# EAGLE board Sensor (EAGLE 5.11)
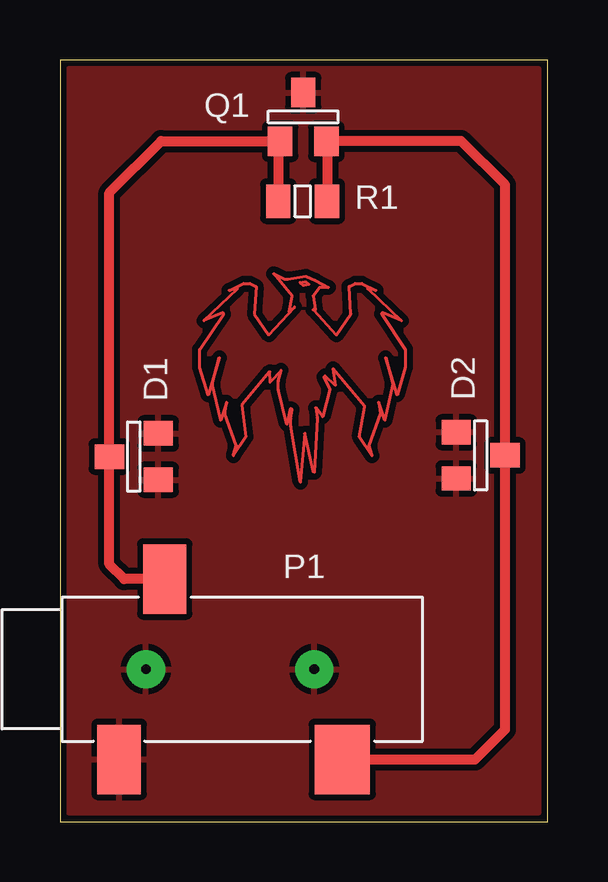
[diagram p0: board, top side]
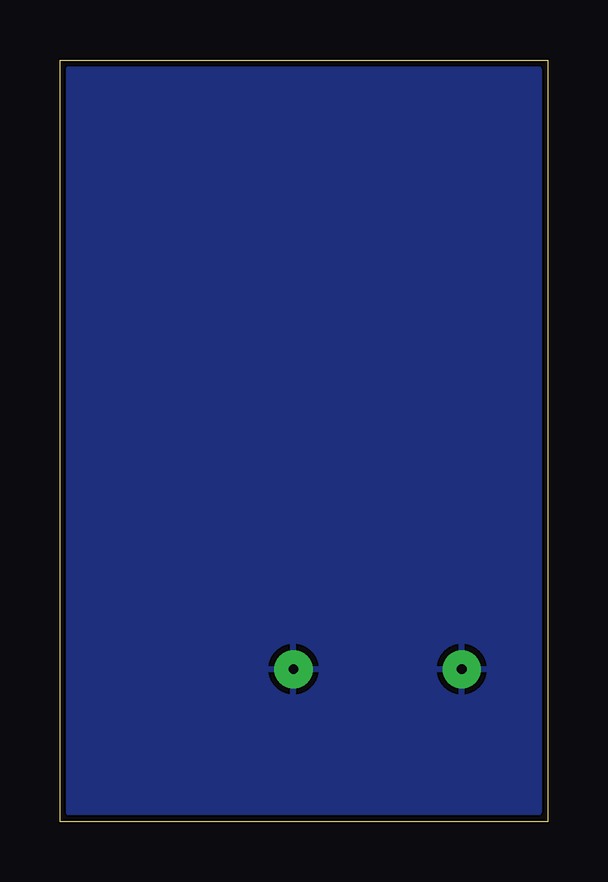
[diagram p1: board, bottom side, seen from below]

Size 20.32 x 31.75 mm. Coordinates in mm from the lower left corner, seen from the top.
Outline: 0,0 20.32,0 20.32,31.75 0,31.75 0,0
Copper layers (1*2+5*16): Top 0.035mm / dielectric 0.5mm / Route2 0.035mm / dielectric 0.5mm / Route5 0.035mm / dielectric 0.5mm / Bottom 0.035mm
Design rules "default *": minimum track width 1mil, minimum drill 1mil, track to track 8mil, track to pad 8mil, pad to pad 8mil, via to via 8mil, smd to smd 8mil, copper to edge 0mil, drill to drill 8mil, minimum pad ring 1mil, minimum via ring 1mil, stop-mask expansion 4mil, vias tented up to drill 16mil, thermal gap 10mil

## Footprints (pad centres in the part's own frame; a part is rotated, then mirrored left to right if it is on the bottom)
SOT23 = smd 1.016 x 1.219: 1 -0.94,1.016; 2 0.991,1.016; 3 0.025,-1.016
3.5MMST_RA_SMT-3 = smd 1.803 x 2.896: P$1 5.131,3.759; P$2 3.226,-3.759 | smd 2.311 x 2.896: P$3 -4.166,3.759 | drill 0.406 pad 1.587 round: P$5 -2.997,0; P$6 4.013,0
C0805 = smd 1.397 x 1.016: P$1 0,-1.016; P$2 0,1.016

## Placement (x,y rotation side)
D1  [SOT23]  3.07,15.24 270 top
D2  [SOT23]  17.53,15.24 90 top
E$1  [PHOENIX_LOGO_CU]  10.11,19.68 0 top
P1  [3.5MMST_RA_SMT-3]  7.59,6.35 180 top
Q1  [SOT23]  10.16,29.38 180 top
R1  [C0805]  10.11,25.86 90 top

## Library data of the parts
D1 D2 Q1 R1 = RF
E$1 P1 = WJC

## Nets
$GND: D1.1 D1.2 D2.1 D2.2 P1.P$1 P1.P$5 P1.P$6 Q1.3
S$1: D2.3 P1.P$3 Q1.1 R1.P$1
S$3: D1.3 P1.P$2 Q1.2 R1.P$2

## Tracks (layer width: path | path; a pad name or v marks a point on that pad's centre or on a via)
$GND
  pour Top (isolate 0.254): 0.38,0.38 19.94,0.38 19.94,31.37 0.38,31.37
  pour Bottom (isolate 0.254): 0.38,0.38 19.94,0.38 19.94,31.37 0.38,31.37
S$1
  Top 0.406: P1.P$3 17.3,2.59 18.54,3.83 D2.3 18.54,26.54 16.71,28.37 11.11,28.37 Q1.1 11.12,28.33 R1.P$1
S$3
  Top 0.406: P1.P$2 2.67,10.11 2.06,10.72 D1.3 2.06,26.21 4.22,28.37 9.16,28.37 Q1.2 9.09,28.28 R1.P$2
